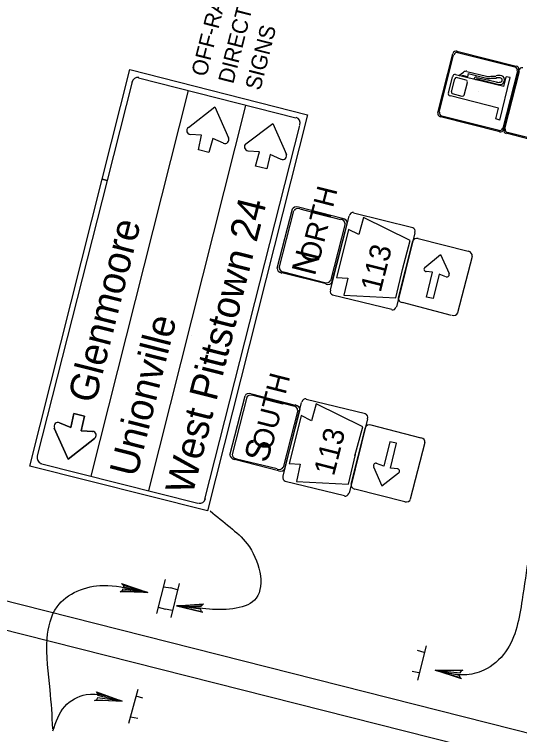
# Model space of a CAD drawing. Extents: x 640994 to 644422, y 298458 to 299646.
# Drawn here: x 643138.7 to 643234.7, y 299430.9 to 299567.7 of the extents above; entities that cross this region are included whole.
import ezdxf

# ---------------------------------------------------------------- set-up
doc = ezdxf.new("R2010")
doc.units = 0
doc.layers.add('2', color=7, linetype='Continuous')

msp = doc.modelspace()

# ---------------------------------------------------------------- linework, layer by layer
at = {"layer": '2'}
for p, q in [((643219.19, 299549), (643222.06, 299560.25)), ((643222.81, 299560.75), (643234.06, 299557.88)), ((643222.94, 299560.5), (643233.81, 299557.75)), ((643219.44, 299549.13), (643222.19, 299560)), ((643155.44, 299536.43), (643160.69, 299557.25)), ((643160.69, 299557.25), (643194.44, 299548.63)), ((643231.69, 299554), (643222.56, 299556.25)), ((643223.19, 299556.13), (643224.06, 299556.75)), ((643223.94, 299556.13), (643223.69, 299556)), ((643224.81, 299555.88), (643223.94, 299556.13)), ((643224.69, 299556.88), (643228.44, 299556)), ((643224.94, 299556.5), (643224.81, 299555.88)), ((643224.94, 299556.5), (643228.44, 299555.63)), ((643234.31, 299557), (643231.56, 299546.13)), ((643234.56, 299557.13), (643231.69, 299545.88)), ((643231.69, 299545.88), (643234.56, 299557.13)), ((643231.94, 299546), (643234.69, 299556.88)), ((643161.19, 299555.13), (643156.37, 299536.19)), ((643192.19, 299548), (643162.31, 299555.63)), ((643221.19, 299552.75), (643221.94, 299555.88)), ((643221.81, 299553), (643222.44, 299555.5)), ((643224.56, 299555.25), (643222.69, 299555.75)), ((643224.19, 299552.38), (643224.81, 299554.75)), ((643226.06, 299555.38), (643226.19, 299555.63)), ((643226.44, 299555.25), (643226.44, 299555.38)), ((643226.56, 299555.75), (643230.31, 299554.88)), ((643226.56, 299555.5), (643230.69, 299554.38)), ((643229.31, 299556), (643230.19, 299556)), ((643229.31, 299555.63), (643230.31, 299555.63)), ((643230.94, 299547.63), (643232.94, 299555.75)), ((643231.69, 299554), (643232.19, 299555.88)), ((643232.94, 299555.75), (643232.19, 299555.88)), ((643153.31, 299480), (643171.81, 299553.25)), ((643230.69, 299549.88), (643221.56, 299552.25)), ((643223.81, 299552.13), (643221.94, 299552.63)), ((643226.94, 299553.13), (643226.94, 299553.13)), ((643164.31, 299477.25), (643182.69, 299550.38)), ((643171.81, 299546.25), (643176.81, 299550.13)), ((643176.81, 299550.13), (643179.44, 299544.25)), ((643230.19, 299547.88), (643230.69, 299549.88)), ((643194.44, 299548.63), (643175.44, 299473.38)), ((643230.94, 299545.38), (643219.69, 299548.25)), ((643230.81, 299545.63), (643219.94, 299548.38)), ((643230.94, 299547.63), (643230.19, 299547.88)), ((643174.94, 299475.63), (643192.94, 299546.63)), ((643182.69, 299543.13), (643187.81, 299547)), ((643187.81, 299547), (643190.44, 299541.13)), ((643243.44, 299542.25), (643232.19, 299545.13)), ((643243.31, 299542.5), (643232.44, 299545.25)), ((643174.31, 299544.75), (643172.06, 299544.88)), ((643173.69, 299542), (643174.31, 299544.75)), ((643176.44, 299544.13), (643175.69, 299541.5)), ((643178.44, 299543.25), (643176.44, 299544.13)), ((643175.69, 299541.5), (643173.69, 299542)), ((643185.31, 299541.63), (643183.06, 299541.75)), ((643184.56, 299538.88), (643185.31, 299541.63)), ((643187.31, 299541.13), (643186.69, 299538.38)), ((643189.44, 299540.13), (643187.31, 299541.13)), ((643186.69, 299538.38), (643184.56, 299538.88)), ((643141.69, 299481.88), (643155.44, 299536.43)), ((643156.37, 299536.19), (643143.06, 299483.88)), ((643156.37, 299536.19), (643155.44, 299536.43)), ((643155.44, 299536.43), (643156.37, 299536.19)), ((643188.69, 299519.5), (643191.56, 299530.75)), ((643189.06, 299519.5), (643191.81, 299530.38)), ((643192.69, 299531.13), (643201.06, 299529)), ((643192.94, 299530.75), (643200.69, 299528.75)), ((643198.81, 299515.38), (643202.31, 299529.38)), ((643203.19, 299530), (643214.44, 299527.25)), ((643205.06, 299529.13), (643204.19, 299525.88)), ((643213.94, 299524.75), (643205.06, 299529.13)), ((643201.56, 299528), (643198.81, 299517.13)), ((643201.94, 299528.13), (643199.06, 299516.88)), ((643202.19, 299526.88), (643201.06, 299522.25)), ((643204.19, 299525.88), (643202.19, 299526.88)), ((643214.81, 299526.25), (643211.31, 299512.13)), ((643211.69, 299513.88), (643214.44, 299524.63)), ((643211.69, 299513.88), (643214.44, 299524.63)), ((643211.69, 299513.88), (643214.44, 299524.63)), ((643212.44, 299519.25), (643213.94, 299524.75)), ((643215.44, 299525.13), (643224.94, 299522.75)), ((643215.44, 299525.13), (643224.94, 299522.75)), ((643215.44, 299525.13), (643224.94, 299522.75)), ((643195.31, 299523.75), (643195.31, 299523.75)), ((643201.06, 299522.25), (643199.94, 299517.75)), ((643216.69, 299519.63), (643219.69, 299522.13)), ((643219.69, 299522.13), (643221.31, 299518.5)), ((643225.69, 299521.75), (643222.94, 299511)), ((643225.69, 299521.75), (643222.94, 299511)), ((643225.69, 299521.75), (643222.94, 299511)), ((643211.19, 299513.88), (643212.56, 299519.5)), ((643197.94, 299516.5), (643189.56, 299518.63)), ((643197.69, 299516.75), (643189.94, 299518.75)), ((643199.94, 299517.75), (643202.06, 299517.63)), ((643218.19, 299518.75), (643216.94, 299518.88)), ((643217.06, 299514), (643218.19, 299518.75)), ((643219.44, 299518.38), (643218.31, 299513.75)), ((643218.69, 299517.88), (643218.69, 299517.88)), ((643218.69, 299517.88), (643218.69, 299517.88)), ((643218.69, 299517.88), (643218.69, 299517.88)), ((643220.69, 299517.88), (643219.44, 299518.38)), ((643202.06, 299517.63), (643201.31, 299514.38)), ((643210.44, 299511.63), (643199.19, 299514.38)), ((643201.31, 299514.38), (643211.19, 299513.88)), ((643218.31, 299513.75), (643217.06, 299514)), ((643161.56, 299512.38), (643161.56, 299512.38)), ((643221.81, 299510.5), (643212.44, 299513)), ((643221.81, 299510.5), (643212.44, 299513)), ((643221.81, 299510.5), (643212.44, 299513)), ((643210.44, 299511.63), (643210.44, 299511.63)), ((643172.44, 299509.63), (643172.44, 299509.63)), ((643172.44, 299509.63), (643172.44, 299509.63)), ((643172.31, 299506.75), (643172.31, 299506.75)), ((643183.19, 299504), (643183.19, 299504)), ((643183.19, 299504), (643183.19, 299504)), ((643179.69, 299484), (643182.56, 299495.25)), ((643180.19, 299484.13), (643182.94, 299495)), ((643183.81, 299495.63), (643192.06, 299493.5)), ((643184.06, 299495.38), (643191.69, 299493.38)), ((643194.19, 299494.63), (643205.44, 299491.88)), ((643189.81, 299480), (643193.31, 299494)), ((643196.06, 299493.75), (643195.19, 299490.5)), ((643204.94, 299489.38), (643196.06, 299493.75)), ((643149.44, 299489.25), (643150.06, 299491.88)), ((643150.06, 299491.88), (643149.44, 299489.25)), ((643150.06, 299491.88), (643152.06, 299491.38)), ((643152.06, 299491.38), (643150.06, 299491.88)), ((643192.56, 299492.5), (643189.81, 299481.63)), ((643192.94, 299492.63), (643190.06, 299481.38)), ((643152.06, 299491.38), (643151.44, 299488.63)), ((643151.44, 299488.63), (643152.06, 299491.38)), ((643193.19, 299491.5), (643192.06, 299486.88)), ((643195.19, 299490.5), (643193.19, 299491.5)), ((643205.81, 299490.88), (643202.31, 299476.75)), ((643148.94, 299483.25), (643146.31, 299489.13)), ((643146.31, 299489.13), (643148.94, 299483.25)), ((643147.31, 299490.13), (643149.44, 299489.25)), ((643149.44, 299489.25), (643147.31, 299490.13)), ((643202.69, 299478.5), (643205.44, 299489.25)), ((643202.69, 299478.5), (643205.44, 299489.25)), ((643202.69, 299478.5), (643205.44, 299489.25)), ((643203.44, 299483.88), (643204.94, 299489.38)), ((643206.44, 299489.75), (643215.94, 299487.25)), ((643206.44, 299489.75), (643215.94, 299487.25)), ((643206.44, 299489.75), (643215.94, 299487.25)), ((643151.44, 299488.63), (643153.69, 299488.5)), ((643153.69, 299488.5), (643151.44, 299488.63)), ((643153.56, 299488.5), (643153.69, 299488.5)), ((643186.31, 299488.38), (643186.31, 299488.38)), ((643153.94, 299487.13), (643148.94, 299483.25)), ((643148.94, 299483.25), (643153.94, 299487.13)), ((643192.06, 299486.88), (643190.94, 299482.38)), ((643210.06, 299486.5), (643208.94, 299481.88)), ((643211.31, 299486.25), (643210.06, 299486.5)), ((643216.69, 299486.38), (643213.94, 299475.63)), ((643216.69, 299486.38), (643213.94, 299475.63)), ((643216.69, 299486.38), (643213.94, 299475.63)), ((643197.81, 299485.38), (643197.81, 299485.38)), ((643197.81, 299485.38), (643197.81, 299485.38)), ((643210.19, 299481.5), (643211.31, 299486.25)), ((643202.19, 299478.5), (643203.56, 299484.13)), ((643143.69, 299482.38), (643173.56, 299474.88)), ((643188.94, 299481), (643180.56, 299483.13)), ((643188.69, 299481.38), (643180.94, 299483.25)), ((643190.94, 299482.38), (643193.06, 299482.25)), ((643193.06, 299482.25), (643192.31, 299479)), ((643208.94, 299481.88), (643207.56, 299482.38)), ((643209.69, 299482.38), (643209.69, 299482.38)), ((643209.69, 299482.38), (643209.69, 299482.38)), ((643175.44, 299473.38), (643141.69, 299481.88)), ((643206.94, 299481.75), (643208.56, 299478.13)), ((643211.56, 299481.38), (643210.19, 299481.5)), ((643208.56, 299478.13), (643211.69, 299480.63)), ((643201.44, 299476.25), (643190.19, 299479)), ((643192.31, 299479), (643202.19, 299478.5)), ((643212.94, 299475.13), (643203.44, 299477.5)), ((643212.94, 299475.13), (643203.44, 299477.5)), ((643212.94, 299475.13), (643203.44, 299477.5)), ((643201.44, 299476.25), (643201.44, 299476.25)), ((643244.81, 299429), (643099.31, 299465.88)), ((643165.81, 299453.88), (643167.44, 299460.38)), ((643167.06, 299459), (643168.44, 299458.75)), ((643170.06, 299459.63), (643168.44, 299453.13)), ((643169.69, 299458.38), (643168.44, 299458.75)), ((643284.81, 299413.38), (643110.81, 299457.38)), ((643166.06, 299455.13), (643167.44, 299454.75)), ((643168.69, 299454.5), (643167.44, 299454.75)), ((643216.94, 299447.75), (643215.31, 299441.25)), ((643216.56, 299446.5), (643215.31, 299446.88)), ((643215.56, 299442.63), (643214.31, 299442.88)), ((643162.19, 299439.5), (643160.44, 299433)), ((643161.81, 299438.25), (643163.06, 299437.88)), ((643160.81, 299434.25), (643162.19, 299434))]:
    msp.add_line(p, q, dxfattribs=at)
for points in [[(643159.44, 299459.25), (643159.44, 299459), (643164.06, 299457.88), (643159.44, 299459.25), (643159.06, 299459.63), (643164.06, 299457.88), (643159.31, 299458.5), (643159.19, 299458.25), (643164.06, 299457.88), (643158.81, 299458), (643159.19, 299458.25)], [(643174.31, 299454.25), (643174.19, 299454.75), (643169.56, 299455.38), (643174.31, 299454.25), (643174.56, 299454.13), (643169.56, 299455.38), (643174.19, 299455.25), (643174.44, 299455.5), (643169.56, 299455.38), (643174.69, 299455.75), (643174.44, 299455.5)], [(643223.44, 299441.75), (643223.31, 299442.13), (643218.69, 299443.13), (643223.44, 299441.75), (643223.69, 299441.5), (643218.69, 299443.13), (643223.44, 299442.63), (643223.69, 299443), (643218.69, 299443.13), (643223.94, 299443.13), (643223.69, 299443)], [(643154.44, 299438.75), (643154.56, 299438.38), (643159.19, 299437.25), (643154.44, 299438.75), (643154.31, 299439), (643159.19, 299437.25), (643154.56, 299437.88), (643154.31, 299437.5), (643159.19, 299437.25), (643153.94, 299437.38), (643154.31, 299437.5)]]:
    msp.add_lwpolyline(points, dxfattribs=at)
for centre, radius, start, end in [((643222.68, 299560.12), 0.645, 75.7754, 165.7754), ((643222.82, 299559.89), 0.597, 75.7754, 165.7754), ((643233.7, 299557.13), 0.597, 345.7754, 75.7754), ((643233.93, 299557.27), 0.645, 345.7754, 75.7754), ((643235.18, 299556.95), 0.645, 75.7754, 165.7754), ((643222.46, 299555.8), 0.486, 83.6778, 164.7031), ((643224.57, 299555.92), 0.991, 81.3158, 122.9841), ((643230.77, 299553.42), 2.68, 78.1727, 101.1253), ((643231.04, 299555.25), 0.84, 344.9893, 71.1198), ((643222.7, 299555.43), 0.274, 92.8615, 169.1523), ((643224.4, 299554.88), 0.392, 341.4902, 59.3145), ((643226.45, 299555.5), 0.318, 75.201, 153.6335), ((643226.53, 299555.37), 0.0771, 64.9719, 167.615), ((643228.89, 299558.9), 3.35, 262.3862, 278.0519), ((643228.89, 299558.9), 2.98, 262.3862, 278.0519), ((643230.66, 299554.09), 1.59, 68.02, 103.4387), ((643230.69, 299556.33), 1.53, 256.8807, 285.2561), ((643230.95, 299555.32), 0.953, 254.9902, 342.4176), ((643231.06, 299555.24), 0.381, 275.7441, 58.872), ((643221.58, 299552.63), 0.415, 157.4008, 262.3628), ((643222.02, 299552.88), 0.249, 154.0614, 244.0323), ((643223.87, 299552.49), 0.314, 262.0164, 342.4308), ((643219.83, 299548.87), 0.645, 165.7754, 255.7754), ((643220.06, 299549.01), 0.597, 165.7754, 255.7754), ((643172.22, 299545.63), 0.745, 125.638, 266.3035), ((643230.94, 299546.25), 0.597, 255.7754, 345.7754), ((643231.08, 299546.02), 0.645, 255.7754, 345.7754), ((643232.33, 299545.7), 0.645, 165.7754, 255.7754), ((643232.56, 299545.84), 0.597, 165.7754, 255.7754), ((643178.75, 299543.94), 0.745, 244.0264, 27.9331), ((643183.19, 299542.56), 0.745, 125.638, 266.3035), ((643189.72, 299540.86), 0.745, 244.0264, 27.9331), ((643216.99, 299519.32), 0.45, 126.1169, 265.3481), ((643220.91, 299518.29), 0.45, 247.2918, 24.1455), ((643147.01, 299489.46), 0.745, 64.0264, 207.9331), ((643147.01, 299489.46), 0.745, 64.0264, 207.9331), ((643153.54, 299487.76), 0.745, 305.638, 86.3035), ((643153.54, 299487.76), 0.745, 305.638, 86.3035), ((643207.41, 299481.99), 0.46, 64.0256, 207.9322), ((643211.44, 299480.95), 0.46, 305.6371, 86.3026)]:
    msp.add_arc(centre, radius, start, end, dxfattribs=at)
for centre, major_axis, ratio, start_param, end_param in [((643162.09, 299554.54), (-0.29, -1.16), 0.890186, 3.141593, 4.712389), ((643191.96, 299546.97), (0.29, 1.16), 0.890186, 4.712389, 6.283185), ((643192.57, 299530.45), (-1.04, 0.26), 0.6, 4.712389, 6.283185), ((643192.83, 299530.19), (-0.964, 0.244), 0.6, 4.712389, 6.283185), ((643202.95, 299529.27), (-0.198, -0.782), 0.8, 3.141593, 4.712389), ((643200.55, 299528.23), (-0.964, 0.244), 0.6, 3.141593, 4.712389), ((643200.91, 299528.34), (-1.04, 0.26), 0.6, 3.141593, 4.712389), ((643214.21, 299526.41), (0.198, 0.782), 0.8, 4.712389, 6.283185), ((643215.3, 299524.43), (-0.903, 0.229), 0.769266, 4.712389, 6.283185), ((643215.3, 299524.43), (-0.903, 0.229), 0.769266, 4.712389, 6.283185), ((643215.3, 299524.43), (-0.903, 0.229), 0.769266, 4.712389, 6.283185), ((643224.78, 299522.03), (-0.903, 0.229), 0.769266, 3.141593, 4.712389), ((643224.78, 299522.03), (-0.903, 0.229), 0.769266, 3.141593, 4.712389), ((643224.78, 299522.03), (-0.903, 0.229), 0.769266, 3.141593, 4.712389), ((643189.72, 299519.2), (1.04, -0.26), 0.6, 3.141593, 4.712389), ((643190.07, 299519.3), (0.964, -0.244), 0.6, 3.141593, 4.712389), ((643197.79, 299517.35), (0.964, -0.244), 0.6, 4.712389, 6.283185), ((643198.05, 299517.08), (1.04, -0.26), 0.6, 4.712389, 6.283185), ((643199.39, 299515.2), (-0.198, -0.782), 0.8, 4.712389, 6.283185), ((643212.57, 299513.66), (0.903, -0.229), 0.769266, 3.141593, 4.712389), ((643212.57, 299513.66), (0.903, -0.229), 0.769266, 3.141593, 4.712389), ((643212.57, 299513.66), (0.903, -0.229), 0.769266, 3.141593, 4.712389), ((643210.64, 299512.35), (0.198, 0.782), 0.8, 3.141593, 4.712389), ((643222.05, 299511.26), (0.903, -0.229), 0.769266, 4.712389, 6.283185), ((643222.05, 299511.26), (0.903, -0.229), 0.769266, 4.712389, 6.283185), ((643222.05, 299511.26), (0.903, -0.229), 0.769266, 4.712389, 6.283185), ((643183.59, 299495.02), (-1.04, 0.26), 0.6, 4.712389, 6.283185), ((643183.85, 299494.76), (-0.964, 0.244), 0.6, 4.712389, 6.283185), ((643193.95, 299493.89), (-0.198, -0.782), 0.8, 3.141593, 4.712389), ((643191.57, 299492.8), (-0.964, 0.244), 0.6, 3.141593, 4.712389), ((643191.93, 299492.91), (-1.04, 0.26), 0.6, 3.141593, 4.712389), ((643205.21, 299491.04), (0.198, 0.782), 0.8, 4.712389, 6.283185), ((643206.32, 299489), (-0.903, 0.229), 0.769266, 4.712389, 6.283185), ((643206.32, 299489), (-0.903, 0.229), 0.769266, 4.712389, 6.283185), ((643206.32, 299489), (-0.903, 0.229), 0.769266, 4.712389, 6.283185), ((643215.8, 299486.6), (-0.903, 0.229), 0.769266, 3.141593, 4.712389), ((643215.8, 299486.6), (-0.903, 0.229), 0.769266, 3.141593, 4.712389), ((643215.8, 299486.6), (-0.903, 0.229), 0.769266, 3.141593, 4.712389), ((643144.13, 299483.59), (-0.29, -1.16), 0.890186, 4.712389, 6.283185), ((643180.74, 299483.77), (1.04, -0.26), 0.6, 3.141593, 4.712389), ((643181.09, 299483.87), (0.964, -0.244), 0.6, 3.141593, 4.712389), ((643188.81, 299481.92), (0.964, -0.244), 0.6, 4.712389, 6.283185), ((643189.08, 299481.65), (1.04, -0.26), 0.6, 4.712389, 6.283185), ((643190.39, 299479.82), (-0.198, -0.782), 0.8, 4.712389, 6.283185), ((643203.59, 299478.23), (0.903, -0.229), 0.769266, 3.141593, 4.712389), ((643203.59, 299478.23), (0.903, -0.229), 0.769266, 3.141593, 4.712389), ((643203.59, 299478.23), (0.903, -0.229), 0.769266, 3.141593, 4.712389), ((643201.64, 299476.97), (0.198, 0.782), 0.8, 3.141593, 4.712389), ((643174.01, 299476.02), (0.29, 1.16), 0.890186, 3.141593, 4.712389), ((643213.07, 299475.83), (0.903, -0.229), 0.769266, 4.712389, 6.283185), ((643213.07, 299475.83), (0.903, -0.229), 0.769266, 4.712389, 6.283185), ((643213.07, 299475.83), (0.903, -0.229), 0.769266, 4.712389, 6.283185)]:
    msp.add_ellipse(centre, major_axis=major_axis, ratio=ratio, start_param=start_param, end_param=end_param, dxfattribs=at)
for points in [[(643249.06, 299537.63), (643245.56, 299503.5), (643237.81, 299472.63), (643235.19, 299456.5), (643232.06, 299446.63), (643227.94, 299443.13), (643224.19, 299442.25), (643218.69, 299443.13)], [(643175.94, 299473.38), (643179.72, 299470.28), (643182.98, 299467.13), (643184.68, 299456.84), (643175.78, 299454.72), (643170.94, 299455.38)], [(643146.06, 299432), (643145.52, 299439.4), (643144.97, 299449.15), (643146.85, 299455.2), (643155.62, 299459.25), (643162.22, 299458.17)], [(643146.06, 299431.63), (643148.31, 299436.25), (643152.35, 299438.49), (643159.19, 299437.25)]]:
    msp.add_spline(points, degree=3, dxfattribs=at)

# ---------------------------------------------------------------- texts
for s, height, rotation, p in [('DIRECTIONAL', 3, 75.7789, (643180.31, 299554.38)), ('OFF-RAMP', 3, 75.7789, (643175.19, 299555.75)), ('SIGNS', 3, 75.7789, (643185.44, 299553.13)), ('ORTH', 3.875, 75.7783, (643196.56, 299520.25)), ('West Pittstown 24', 5.3752, 75.7788, (643172.56, 299476.25)), ('Glenmoore   ', 5.3752, 75.7788, (643154.06, 299493.63)), ('113', 4, 75.7777, (643208.31, 299514.75)), ('N', 4.63, 75.7284, (643195.81, 299517.88)), ('Unionville', 5.375, 75.7788, (643161.94, 299479.63)), ('OUTH', 3.875, 75.7783, (643187.56, 299484.75)), ('113', 4, 75.7777, (643199.44, 299479.88)), ('S', 4.63, 75.7284, (643186.81, 299482.38))]:
    msp.add_text(s, height=height, rotation=rotation, dxfattribs=at).set_placement(p)

doc.saveas('drawing.dxf')
